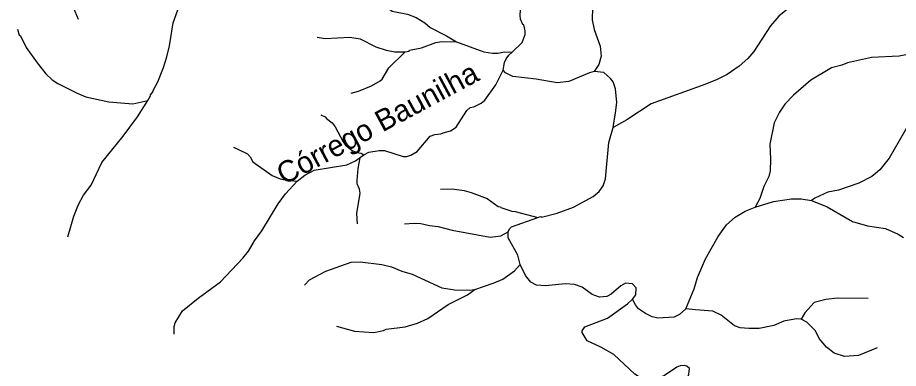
# Model space of a CAD drawing. Extents: x 393 to 446.6, y 8175.5 to 8231.
# Drawn here: x 405.97 to 412.53, y 8197.16 to 8199.78 of the extents above; entities that cross this region are included whole.
import ezdxf
from ezdxf.enums import TextEntityAlignment as Align

# ---------------------------------------------------------------- set-up
doc = ezdxf.new("R2010")
doc.units = 0
doc.header["$LTSCALE"] = 0.064
doc.linetypes.add('LONG_DASHED', pattern=[7.5, 6, -1.5])
doc.layers.add('61', color=7, linetype='Continuous')
doc.layers.add('7', color=7, linetype='Continuous', lineweight=25)
doc.layers.add('9', color=7, linetype='LONG_DASHED', lineweight=25)

msp = doc.modelspace()

# ---------------------------------------------------------------- linework, layer by layer
at = {"layer": '7'}
msp.add_line((408.5235, 8198.7395), (408.5484, 8198.7579), dxfattribs=at)
for points in [[(412.0495, 8200.5384), (411.8749, 8200.5504), (411.6908, 8200.5827), (411.6133, 8200.6037), (411.5132, 8200.6182), (411.4454, 8200.6198), (411.3162, 8200.6101), (411.1838, 8200.5859), (411.0223, 8200.5197), (410.7268, 8200.3066), (410.5959, 8200.2016), (410.441, 8200.095), (410.3295, 8199.9917), (410.3004, 8199.9546), (410.2665, 8199.8932), (410.2536, 8199.8544), (410.2488, 8199.764), (410.2649, 8199.693), (410.3101, 8199.5686), (410.3166, 8199.4943), (410.2988, 8199.4314), (410.2652, 8199.3784)], [(409.6549, 8199.5242), (409.7288, 8199.5944), (409.7514, 8199.6542), (409.7514, 8199.6833), (409.7401, 8199.7268), (409.7336, 8199.7301), (409.7159, 8199.7705), (409.7127, 8199.7995), (409.7224, 8199.919), (409.6933, 8200.0095), (409.6287, 8200.1548), (409.6222, 8200.1871), (409.6271, 8200.2517), (409.6949, 8200.4261), (409.7104, 8200.495)], [(412.3168, 8200.1258), (412.2931, 8200.1031), (412.1623, 8200.0369), (411.9362, 8199.9739), (411.8478, 8199.9279), (411.7812, 8199.8932), (411.7037, 8199.8447), (411.6391, 8199.793), (411.5778, 8199.7204), (411.4534, 8199.5283), (411.4098, 8199.4766), (411.3452, 8199.42), (411.2548, 8199.3571), (411.1805, 8199.3183), (411.0901, 8199.2811), (410.6896, 8199.139), (410.5088, 8199.0179), (410.4061, 8198.9623)], [(408.7087, 8199.8607), (408.7309, 8199.8421), (408.7405, 8199.8431), (408.7616, 8199.8302), (408.8746, 8199.806), (408.9392, 8199.7817), (409.0038, 8199.7414), (409.0426, 8199.7075), (409.1653, 8199.6461), (409.2389, 8199.5992)], [(408.2024, 8199.6351), (408.261, 8199.6251), (408.4451, 8199.6348), (408.5226, 8199.6219), (408.6389, 8199.5637), (408.7164, 8199.5395), (408.781, 8199.5266), (408.8578, 8199.5255)], [(408.8578, 8199.5255), (408.8869, 8199.5313), (408.8907, 8199.5379), (408.978, 8199.5557), (409.0845, 8199.5944), (409.1298, 8199.6041), (409.2389, 8199.5992)], [(409.2389, 8199.5992), (409.443, 8199.5266), (409.5076, 8199.5169), (409.5464, 8199.5169), (409.598, 8199.5266), (409.6536, 8199.5243), (409.6549, 8199.5242)], [(408.4548, 8199.2177), (408.5097, 8199.2327), (408.6066, 8199.2715), (408.6712, 8199.3102), (408.6856, 8199.3231), (408.7357, 8199.4055), (408.8578, 8199.5255)], [(409.5884, 8199.3893), (409.5966, 8199.4452), (409.6106, 8199.4742), (409.6304, 8199.501), (409.6549, 8199.5242)], [(408.5484, 8198.7579), (408.5872, 8198.7773), (408.6647, 8198.7902), (408.7035, 8198.7902), (408.8423, 8198.745), (408.8698, 8198.745), (408.9005, 8198.7547), (408.9457, 8198.7822), (409.0426, 8198.8968), (409.0781, 8198.9097), (409.1217, 8198.913), (409.1394, 8198.9227), (409.1943, 8198.9356), (409.2363, 8198.963), (409.317, 8199.089), (409.3413, 8199.11), (409.3687, 8199.1164), (409.4236, 8199.1423), (409.4511, 8199.1665), (409.5318, 8199.2796), (409.5884, 8199.3893)], [(410.2652, 8199.3784), (410.2302, 8199.3691), (410.076, 8199.3054), (409.9888, 8199.2941), (409.8338, 8199.3215), (409.6594, 8199.3409), (409.6036, 8199.3695), (409.5884, 8199.3893)], [(410.4061, 8198.9623), (410.4248, 8199.0697), (410.4329, 8199.1472), (410.4232, 8199.2505), (410.4054, 8199.3022), (410.3877, 8199.328), (410.3376, 8199.3716), (410.2652, 8199.3784)], [(408.2283, 8199.0551), (408.2621, 8199.0411), (408.2707, 8199.0276), (408.3143, 8198.9953), (408.3368, 8198.9663), (408.395, 8198.8533), (408.4128, 8198.8307), (408.4628, 8198.7902), (408.5, 8198.7741), (408.5302, 8198.77), (408.5484, 8198.7579)], [(409.846, 8198.2889), (409.8667, 8198.2963), (409.8726, 8198.2929), (409.9888, 8198.322), (410.1116, 8198.3672), (410.2569, 8198.4463), (410.3021, 8198.4834), (410.3327, 8198.5271), (410.3489, 8198.5788), (410.3747, 8198.85), (410.4061, 8198.9623)], [(407.5793, 8198.8138), (407.6154, 8198.7963), (407.6829, 8198.7644), (407.7038, 8198.7434), (407.7217, 8198.7063), (407.867, 8198.6029), (407.9251, 8198.5787), (407.9768, 8198.5674), (408.0527, 8198.5603)], [(408.0527, 8198.5603), (408.1092, 8198.6046), (408.1802, 8198.6433), (408.4225, 8198.6837), (408.4871, 8198.7127), (408.5235, 8198.7395)], [(408.5012, 8198.2425), (408.4967, 8198.3204), (408.5226, 8198.4705), (408.5177, 8198.5012), (408.5, 8198.54), (408.5, 8198.5658), (408.508, 8198.6563), (408.5228, 8198.7358), (408.5235, 8198.7395)], [(407.1373, 8197.4191), (407.1371, 8197.4775), (407.1435, 8197.5033), (407.2, 8197.5937), (407.3147, 8197.689), (407.4827, 8197.8101), (407.6489, 8197.9861), (407.6909, 8198.0394), (407.7345, 8198.1169), (407.791, 8198.1912), (407.9105, 8198.3914), (407.9654, 8198.4657), (408.0527, 8198.5603)], [(409.1206, 8198.5017), (409.2073, 8198.5028), (409.2977, 8198.4915), (409.3494, 8198.477), (409.4689, 8198.4318), (409.5496, 8198.372), (409.5674, 8198.3688), (409.569, 8198.364), (409.6529, 8198.3365), (409.6772, 8198.3349), (409.846, 8198.2889)], [(408.8534, 8198.2424), (408.9231, 8198.2477), (408.9747, 8198.2445), (409.0393, 8198.2299), (409.1039, 8198.2235), (409.2073, 8198.1944), (409.4915, 8198.1443), (409.569, 8198.154), (409.624, 8198.1843)], [(409.624, 8198.1843), (409.6344, 8198.2064), (409.6496, 8198.2192), (409.846, 8198.2889)], [(409.714, 8197.9393), (409.6966, 8198.008), (409.6239, 8198.1395), (409.624, 8198.1843)], [(408.1066, 8197.7851), (408.1438, 8197.8258), (408.2675, 8197.8908), (408.4547, 8197.957), (408.5226, 8197.9586), (408.6841, 8197.9393), (408.7551, 8197.9215), (408.8326, 8197.8892), (408.9101, 8197.8666), (409.1298, 8197.7665), (409.2266, 8197.7503), (409.3364, 8197.7471), (409.3756, 8197.7527)], [(409.3756, 8197.7527), (409.5205, 8197.802), (409.5851, 8197.8311), (409.6723, 8197.8924), (409.714, 8197.9393)], [(410.5496, 8197.6798), (410.5527, 8197.6825), (410.575, 8197.7132), (410.5766, 8197.7665), (410.5507, 8197.7956), (410.4975, 8197.8004), (410.4635, 8197.781), (410.3925, 8197.718), (410.3586, 8197.7019), (410.3053, 8197.6954), (410.2488, 8197.7164), (410.1745, 8197.7713), (410.118, 8197.7907), (410.0502, 8197.7956), (409.9016, 8197.7794), (409.8354, 8197.7843), (409.7934, 8197.8085), (409.753, 8197.8586), (409.714, 8197.9393)], [(408.3467, 8197.4793), (408.4806, 8197.4419), (408.6227, 8197.4322), (408.697, 8197.4468), (408.7164, 8197.4564), (408.8585, 8197.4742), (408.9489, 8197.5016), (409.0264, 8197.5372), (409.1766, 8197.6405), (409.3203, 8197.7132), (409.3756, 8197.7527)], [(410.7869, 8196.8912), (410.8196, 8196.9296), (410.8915, 8196.993), (410.9545, 8197.077), (410.969, 8197.1222), (410.9738, 8197.1642), (410.956, 8197.1803), (410.9383, 8197.1868), (410.906, 8197.1836), (410.8802, 8197.1739), (410.7898, 8197.1125), (410.7219, 8197.0834), (410.6703, 8197.0802), (410.6186, 8197.0883), (410.5685, 8197.1206), (410.4102, 8197.2691), (410.315, 8197.3224), (410.2133, 8197.3693), (410.1761, 8197.4322), (410.1761, 8197.4435), (410.1955, 8197.4742), (410.3635, 8197.5388), (410.512, 8197.647), (410.5496, 8197.6798)]]:
    msp.add_lwpolyline(points, dxfattribs=at)
at = {"layer": '9'}
for points in [[(406.4254, 8199.7672), (406.3878, 8199.8577), (406.3265, 8200.0143), (406.2812, 8200.1225), (406.2715, 8200.1613), (406.2715, 8200.2937), (406.3184, 8200.481), (406.3587, 8200.573), (406.5106, 8200.8314), (406.7124, 8201.1027), (406.785, 8201.185), (406.8771, 8201.2706), (406.974, 8201.3804), (407.0402, 8201.5048), (407.0515, 8201.5467), (407.0724, 8201.5914), (407.0741, 8201.595)], [(406.9408, 8199.1637), (406.9607, 8199.1976), (406.9578, 8199.2004), (406.9788, 8199.2263), (406.9821, 8199.2424), (407.0159, 8199.3022), (407.0579, 8199.4088), (407.0822, 8199.4895), (407.1015, 8199.5702), (407.1306, 8199.743), (407.1855, 8199.9013), (407.2479, 8200.0398)], [(413.4527, 8199.7675), (413.0376, 8199.68), (412.9907, 8199.6639), (412.8841, 8199.6073), (412.7534, 8199.5508), (412.6387, 8199.5137), (412.537, 8199.4927), (412.3303, 8199.483), (412.1527, 8199.4443), (412.109, 8199.4265), (412.0331, 8199.4071), (411.8797, 8199.3151), (411.749, 8199.2036), (411.686, 8199.1358), (411.6456, 8199.0761), (411.6052, 8198.9954), (411.5729, 8198.8371), (411.5778, 8198.7241), (411.5746, 8198.6385), (411.5647, 8198.5959), (411.5273, 8198.5201), (411.4981, 8198.4315), (411.4639, 8198.3683)], [(405.9709, 8199.6961), (405.9825, 8199.6509), (405.9922, 8199.6445), (406.0342, 8199.5589), (406.1165, 8199.4427), (406.1811, 8199.3619), (406.228, 8199.3167), (406.2716, 8199.2908), (406.4137, 8199.2166), (406.4783, 8199.1907), (406.651, 8199.152), (406.8287, 8199.1375), (406.9408, 8199.1637)], [(406.3441, 8198.1458), (406.3894, 8198.2994), (406.4249, 8198.3882), (406.4605, 8198.4576), (406.5186, 8198.5319), (406.5993, 8198.7015), (406.7576, 8198.8968), (406.8642, 8199.0422), (406.9408, 8199.1637)], [(412.6395, 8199.024), (412.6103, 8198.9913), (412.4627, 8198.7338), (412.3932, 8198.6466), (412.3609, 8198.6175), (412.3319, 8198.5965), (412.2366, 8198.5464), (412.0848, 8198.4948), (412.0057, 8198.4786), (411.9072, 8198.4334), (411.8836, 8198.4158)], [(411.4639, 8198.3683), (411.5993, 8198.4094), (411.7353, 8198.4298), (411.8054, 8198.4286), (411.8836, 8198.4158)], [(410.948, 8197.6098), (411.0093, 8197.7568), (411.0352, 8197.8424), (411.0949, 8197.9813), (411.1886, 8198.1492), (411.2499, 8198.2364), (411.3146, 8198.2913), (411.3905, 8198.3365), (411.4639, 8198.3683)], [(411.8836, 8198.4158), (411.9992, 8198.3704), (412.1882, 8198.259), (412.2996, 8198.2267), (412.4352, 8198.2074), (412.5279, 8198.1663), (412.5688, 8198.1418)], [(410.948, 8197.6098), (410.9008, 8197.5666), (410.8611, 8197.5467), (410.7391, 8197.5403), (410.6977, 8197.5485), (410.646, 8197.5727), (410.5943, 8197.6098), (410.5717, 8197.6373), (410.5496, 8197.6798)], [(412.3047, 8197.6856), (412.0767, 8197.6874), (411.9912, 8197.6793), (411.9023, 8197.6567), (411.8329, 8197.5792), (411.8069, 8197.5321)], [(411.8069, 8197.5321), (411.7719, 8197.5344), (411.6763, 8197.5162), (411.602, 8197.4839), (411.4938, 8197.4613), (411.4179, 8197.4613), (411.3517, 8197.4677), (411.3097, 8197.4807), (411.2096, 8197.5614), (411.1482, 8197.5905), (411.0191, 8197.6018), (410.948, 8197.6098)], [(412.3726, 8197.3182), (412.2334, 8197.2611), (412.13, 8197.253), (412.0525, 8197.2788), (411.9944, 8197.3224), (411.9411, 8197.3886), (411.9137, 8197.4435), (411.8491, 8197.5097), (411.8069, 8197.5321)]]:
    msp.add_lwpolyline(points, dxfattribs=at)

# ---------------------------------------------------------------- texts
at = {"layer": '61'}
msp.add_text('Córrego Baunilha', height=0.16, rotation=28.271, dxfattribs=at).set_placement((408.6882, 8198.9239), align=Align.CENTER)

doc.saveas('drawing.dxf')
